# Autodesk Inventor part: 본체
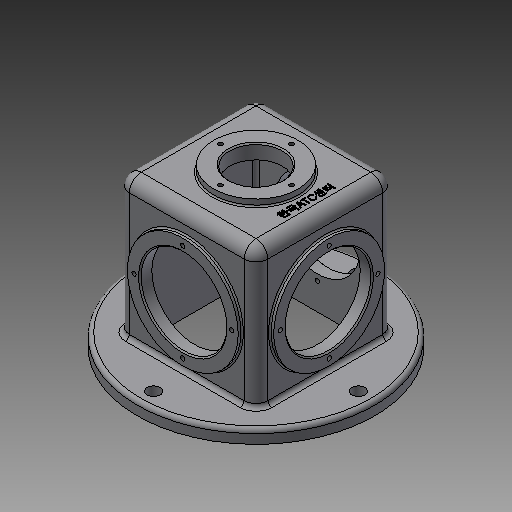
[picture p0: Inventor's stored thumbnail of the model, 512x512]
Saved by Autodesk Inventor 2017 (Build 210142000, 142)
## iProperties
Created: 2018-09
Part Number: 본체
Material: 알루미늄 6061
Document SubType Name: Modeling
Designer: mduedu
Density: 2.71 g/cm^3
Appearance: 기본값
Mass: 1123.29 g
Surface Area: 1247.23 cm^2
Volume: 414.5 cm^3
Author: mduedu
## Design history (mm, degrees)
sketch "스케치1"
  geometry: C1 r 90 at (0, 0); 1 further point
  constraints: 1 centre point, 1 coincident
  dimensions: "d85" = 180 diameter of C1
extrude "돌출1" new body sketch "스케치1" distance "d2" = 10; taper "d3" = 0 deg
sketch "스케치2"
  geometry: L1 (-52.5, -52.5)-(52.5, -52.5); L2 (52.5, -52.5)-(52.5, 52.5); L3 (52.5, 52.5)-(-52.5, 52.5); L4 (-52.5, 52.5)-(-52.5, -52.5); L5 (-52.5, -52.5)-(52.5, 52.5); L6 (52.5, -52.5)-(-52.5, 52.5); 1 further point
  constraints: 12 end point, 2 midpoint, 2 parallel, 1 horizontal, 1 perpendicular
  dimensions: "d4" = 105 distance of L3.end L2.end; "d5" = 105 distance of L2.end L1.end
extrude "돌출2" join sketch "스케치2" distance "d6" = 105; taper "d7" = 0 deg
node "작업 평면1"
sketch "스케치3"
  geometry: L1 (-52.5, 52.5)-(52.5, 52.5) reference; L2 (52.5, 52.5)-(52.5, -52.5) reference; L3 (52.5, -52.5)-(-52.5, -52.5) reference; L4 (-52.5, -52.5)-(-52.5, 52.5) reference; L5 (46.5, 46.5)-(-46.5, 46.5); L6 (-46.5, 46.5)-(-46.5, -46.5); L7 (-46.5, -46.5)-(46.5, -46.5); L8 (46.5, -46.5)-(46.5, 46.5); 1 further point
  constraints: 8 end point, 3 other
  dimensions: "d9" = 6 distance between parallel lines of L5 L1
extrude "돌출3" cut sketch "스케치3" stored distance "d10" = 105; taper "d11" = 0 deg
fillet "모깎기1" dims "d12" = 9
fillet "모깎기2" dims "d13" = 9
fillet "모깎기3" dims "d14" = 3
fillet "모깎기4" dims "d15" = 3
sketch "스케치4"
  geometry: C1 r 32 at (0, 0); 1 further point
  constraints: 1 centre point, 1 coincident
  dimensions: "d86" = 64 diameter of C1
extrude "돌출4" join sketch "스케치4" distance "d18" = 5; taper "d19" = 0 deg
fillet "모깎기6" dims "d21" = 1
sketch "스케치5"
  geometry: C1 r 20 at (0, 0); 1 further point
  constraints: 1 centre point, 1 coincident
  dimensions: "d22" = 40 diameter of C1
extrude "돌출5" cut sketch "스케치5" stored distance "d23" = 5; taper "d24" = 0 deg
sketch "스케치6"
  geometry: L1 (-46.5, -10)-(133.5, -10) reference; C1 r 42 at (43.5, 47.5); 1 further point
  constraints: 1 centre point, 1 vertical alignment
  dimensions: "d87" = 84 diameter of C1; "d88" = 57.5 distance from line of C1.centre L1
extrude "돌출6" join sketch "스케치6" distance "d28" = 3; taper "d29" = 0 deg
sketch "스케치7"
  geometry: C1 r 32.5 at (43.5, 47.5); 1 further point
  constraints: 1 centre point, 1 vertical alignment
  dimensions: "d32" = 65 diameter of C1; "d33" = 57.5 distance of C1.centre point (43.5, -10)
extrude "돌출7" cut sketch "스케치7" stored distance "d34" = 3; taper "d35" = 0 deg
fillet "모깎기9" dims "d36" = 1
sketch "스케치8"
  geometry: L1 (-46.5, -10)-(133.5, -10) reference; C1 r 32.5 at (43.5, 47.5); C2 r 42 at (43.5, 47.5); 4 further points
  constraints: 2 centre point, 2 coincident, 2 vertical alignment, 1 concentric, 1 midpoint
  dimensions: "d40" = 65 diameter of C1; "d90" = 84 diameter of C2; "d91" = 57.5 distance from line of point (43.5, 47.5) L1
extrude "돌출8" join sketch "스케치8" distance "d41" = 3; taper "d42" = 0 deg
extrude "돌출9" cut sketch "스케치8" stored distance "d44" = 3; taper "d45" = 0 deg
fillet "모깎기11" dims "d46" = 1
sketch "스케치14" dims "d93" = 74
  geometry: C1 r 42 at (0, 0) reference; 2 further points
  constraints: 2 vertical alignment, 1 coincident, 2 other
hole "구멍5" sketch "스케치14" at (0, 37) diameter "d95" = 3.242; stored, may be unused: countersink angle "d99" = 90 deg, drill point angle "d101" = 118 deg; dims "d96" = 6, "d97" = 4, "d98" = 2, "d100" = 8
sketch "스케치9" dims "d106" = 74
  geometry: C1 r 32.5 at (43.5, 47.5) reference; 2 further points
  constraints: 2 vertical alignment, 1 coincident, 2 other
hole "구멍1" sketch "스케치9" at (43.5, 84.5) diameter "d47" = 3.242; stored, may be unused: countersink angle "d51" = 90 deg, drill point angle "d53" = 118 deg; dims "d48" = 6, "d49" = 4, "d50" = 2, "d52" = 9
sketch "스케치11" dims "d110" = 54
  geometry: C1 r 20 at (0, 0) reference; 2 further points
  constraints: 2 horizontal alignment, 1 coincident, 2 other
hole "구멍3" sketch "스케치11" at (27, 0) diameter "d61" = 3.242; stored, may be unused: countersink angle "d65" = 90 deg, drill point angle "d67" = 118 deg; dims "d62" = 7, "d63" = 4, "d64" = 2, "d66" = 9
sketch "스케치12" dims "d115" = 155
  geometry: L1 (43.5, -52.5)-(-43.5, -52.5) reference; L2 (-52.5, -43.5)-(-52.5, 43.5) reference; L3 (-43.5, 52.5)-(43.5, 52.5) reference; L4 (52.5, 43.5)-(52.5, -43.5) reference; C1 r 90 at (0, 0) reference; A1 r 9 centre (-43.5, -43.5) between (-52.5, -43.5) and (-43.5, -52.5) reference; A2 r 9 centre (-43.5, 43.5) between (-43.5, 52.5) and (-52.5, 43.5) reference; A3 r 9 centre (43.5, 43.5) between (52.5, 43.5) and (43.5, 52.5) reference; A4 r 9 centre (43.5, -43.5) between (43.5, -52.5) and (52.5, -43.5) reference; 2 further points
  constraints: 2 horizontal alignment, 1 coincident, 2 other
hole "구멍4" sketch "스케치12" at (77.5, 0) diameter "d70" = 10; stored, may be unused: countersink angle "d74" = 90 deg, drill point angle "d76" = 118 deg; dims "d71" = 6, "d72" = 4, "d73" = 2, "d75" = 9
fillet "모깎기13" dims "d77" = 3
fillet "모깎기14" dims "d78" = 3
chamfer "모따기1" distance "d79" = 1; stored, may be unused: second distance "d80" = 2, angle "d81" = 45 deg
sketch "스케치15"
  geometry: 2 further points
  constraints: 1 horizontal alignment, 1 other
  dimensions: "d121" = 38 distance of point (38, 0) point (0, 0)
feature "엠보싱2" sketch "스케치15" dims "d2" = 10, "d3" = 0, "d9" = 6, "d122" = 0.5, "d123" = 0
node "솔리드1"
mirror "대칭1"
pattern_circular "원형 패턴1" dims angle "d104" = 360 deg
pattern_circular "원형 패턴2" dims angle "d108" = 360 deg
mirror "대칭2"
pattern_circular "원형 패턴3" dims angle "d113" = 360 deg
pattern_circular "원형 패턴4" dims angle "d119" = 360 deg
node "투영된 루프1"
node "투영된 루프2"
node "투영된 루프4"
node "투영된 루프5"
other parameters: "d8" = -6
